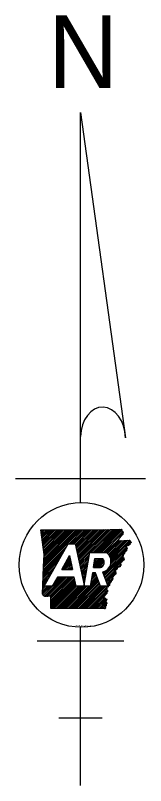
# Model space of a CAD drawing. Extents: x -17668 to 16999, y -17303 to 5867.
# Drawn here: x -11839 to -11576, y -15274 to -13718 of the extents above; entities that cross this region are included whole.
import ezdxf

# ---------------------------------------------------------------- set-up
doc = ezdxf.new("R2010")
doc.units = 0
doc.layers.add('48', color=7, linetype='Continuous')

msp = doc.modelspace()

# ---------------------------------------------------------------- linework, layer by layer
at = {"layer": '48'}
for p, q in [((-11707.1, -13913.8), (-11616.2, -14570.8)), ((-11707.1, -14701.7), (-11707.1, -13913.8)), ((-11838.7, -14653), (-11575.6, -14653)), ((-11786.9, -14758.1), (-11785.9, -14757.1)), ((-11786.6, -14761.2), (-11782.4, -14757.1)), ((-11786.2, -14764.3), (-11778.9, -14757.1)), ((-11785.8, -14767.4), (-11775.4, -14757.1)), ((-11785.4, -14770.5), (-11771.9, -14757.1)), ((-11785, -14773.6), (-11768.5, -14757.1)), ((-11784.6, -14776.7), (-11765, -14757.1)), ((-11784.2, -14779.8), (-11761.5, -14757.1)), ((-11783.9, -14782.9), (-11758, -14757.1)), ((-11783.5, -14786), (-11754.5, -14757.1)), ((-11783.1, -14789.1), (-11751, -14757.1)), ((-11782.7, -14792.2), (-11747.6, -14757.1)), ((-11782.3, -14795.3), (-11744.1, -14757.1)), ((-11781.9, -14798.4), (-11740.6, -14757.1)), ((-11781.8, -14833.1), (-11705.7, -14757)), ((-11781.7, -14829.5), (-11709.2, -14757)), ((-11781.6, -14825.9), (-11712.7, -14757)), ((-11781.5, -14822.3), (-11716.2, -14757)), ((-11781.5, -14801.5), (-11737.1, -14757.1)), ((-11781.3, -14818.7), (-11719.7, -14757)), ((-11781.2, -14815.1), (-11723.2, -14757)), ((-11781.2, -14804.6), (-11733.6, -14757.1)), ((-11781.1, -14811.5), (-11726.7, -14757.1)), ((-11781, -14807.9), (-11730.1, -14757.1)), ((-11730.1, -14784.9), (-11702.2, -14757)), ((-11726.6, -14784.9), (-11698.7, -14757)), ((-11723.1, -14784.9), (-11695.2, -14757)), ((-11719.6, -14784.9), (-11691.7, -14756.9)), ((-11717.5, -14786.2), (-11688.1, -14756.9)), ((-11716.9, -14789.1), (-11684.6, -14756.8)), ((-11716.2, -14791.9), (-11681.1, -14756.7)), ((-11715.6, -14794.8), (-11677.5, -14756.7)), ((-11715, -14797.7), (-11674, -14756.6)), ((-11714.4, -14800.5), (-11670.5, -14756.6)), ((-11713.8, -14803.4), (-11666.9, -14756.5)), ((-11713.2, -14806.3), (-11663.4, -14756.5)), ((-11712.6, -14809.1), (-11659.8, -14756.4)), ((-11711.9, -14812), (-11656.3, -14756.4)), ((-11711.3, -14814.9), (-11652.8, -14756.3)), ((-11710.7, -14817.7), (-11649.2, -14756.3)), ((-11710.1, -14820.6), (-11645.7, -14756.2)), ((-11709.5, -14823.5), (-11642.1, -14756.1)), ((-11685.3, -14802.8), (-11638.5, -14756)), ((-11681.8, -14802.8), (-11635, -14755.9)), ((-11678.3, -14802.8), (-11631.4, -14755.9)), ((-11674.8, -14802.8), (-11627.8, -14755.8)), ((-11671.4, -14802.8), (-11624.3, -14755.7)), ((-11667.9, -14802.8), (-11623.5, -14758.4)), ((-11664.4, -14802.8), (-11621.8, -14760.2)), ((-11660.9, -14802.8), (-11621.4, -14763.2)), ((-11657.4, -14802.8), (-11629.3, -14774.7)), ((-11654.3, -14803.1), (-11630, -14778.8)), ((-11652.4, -14804.7), (-11626.3, -14778.6)), ((-11650.7, -14806.5), (-11622.7, -14778.5)), ((-11649.2, -14808.4), (-11619, -14778.3)), ((-11647.9, -14810.6), (-11615.3, -14778.1)), ((-11646.8, -14813), (-11611.7, -14777.9)), ((-11646, -14815.7), (-11608.3, -14778.1)), ((-11645.5, -14818.7), (-11606.7, -14779.9)), ((-11608.3, -14784.9), (-11605.1, -14781.8)), ((-11781.9, -14836.7), (-11734.9, -14789.7)), ((-11780.8, -14870.7), (-11732.2, -14784.9)), ((-11732.2, -14784.9), (-11717.8, -14784.9)), ((-11646.2, -14826.4), (-11614.6, -14794.8)), ((-11645.5, -14822.2), (-11615, -14791.7)), ((-11782.2, -14843.9), (-11744, -14805.8)), ((-11782.1, -14840.3), (-11739.5, -14797.7)), ((-11745, -14837), (-11729.1, -14808.9)), ((-11731.6, -14813.3), (-11728.8, -14810.5)), ((-11708.9, -14826.4), (-11689.1, -14806.6)), ((-11708.3, -14829.2), (-11689.9, -14810.8)), ((-11688.4, -14802.8), (-11654.7, -14802.8)), ((-11660.6, -14847.8), (-11622, -14809.1)), ((-11659.7, -14850.3), (-11621.4, -14812)), ((-11649.3, -14832.9), (-11622.7, -14806.3)), ((-11618.5, -14802.2), (-11614.2, -14797.9)), ((-11782.4, -14851.1), (-11753.1, -14821.8)), ((-11782.3, -14847.5), (-11748.6, -14813.8)), ((-11744.9, -14837), (-11727, -14819.1)), ((-11741.4, -14837), (-11726.4, -14822)), ((-11740.7, -14829.4), (-11727.6, -14816.2)), ((-11737.9, -14837), (-11725.7, -14824.8)), ((-11736.2, -14821.3), (-11728.2, -14813.4)), ((-11734.4, -14837), (-11725.1, -14827.7)), ((-11707.7, -14832.1), (-11690.6, -14815)), ((-11707, -14835), (-11691.3, -14819.2)), ((-11706.4, -14837.8), (-11692.1, -14823.5)), ((-11705.8, -14840.7), (-11692.8, -14827.7)), ((-11681.1, -14833.2), (-11662.8, -14814.9)), ((-11680.4, -14829), (-11666.3, -14814.9)), ((-11679.7, -14824.8), (-11669.7, -14814.9)), ((-11678.9, -14820.6), (-11673.2, -14814.9)), ((-11678.2, -14816.4), (-11676.7, -14814.9)), ((-11677.9, -14814.9), (-11662.1, -14814.9)), ((-11677.6, -14833.2), (-11660.8, -14816.4)), ((-11674.1, -14833.2), (-11659.7, -14818.7)), ((-11670.7, -14833.2), (-11659, -14821.6)), ((-11667.2, -14833.2), (-11659.3, -14825.3)), ((-11658.7, -14852.8), (-11620.7, -14814.8)), ((-11657.8, -14855.4), (-11620.1, -14817.6)), ((-11632, -14833), (-11627.1, -14828.1)), ((-11782.6, -14858.3), (-11762.2, -14837.9)), ((-11782.5, -14854.7), (-11757.7, -14829.9)), ((-11745, -14837), (-11723.1, -14837)), ((-11730.9, -14837), (-11724.5, -14830.6)), ((-11727.5, -14837), (-11723.9, -14833.4)), ((-11724, -14837), (-11723.3, -14836.3)), ((-11705.2, -14843.6), (-11693.5, -14831.9)), ((-11704.6, -14846.4), (-11694.3, -14836.1)), ((-11704, -14849.3), (-11695, -14840.3)), ((-11684.1, -14850.3), (-11677.2, -14843.4)), ((-11683.4, -14846.1), (-11680.6, -14843.4)), ((-11677.1, -14843.4), (-11682.9, -14843.4)), ((-11681.1, -14833.2), (-11666.7, -14833.2)), ((-11667, -14870.7), (-11677.1, -14843.4)), ((-11662.8, -14841.9), (-11652.2, -14870.7)), ((-11662.5, -14842.7), (-11661.4, -14841.6)), ((-11661.6, -14845.2), (-11654.9, -14838.6)), ((-11656.9, -14857.9), (-11636, -14837)), ((-11655.9, -14860.5), (-11636.4, -14840.9)), ((-11782.9, -14865.5), (-11771.3, -14854)), ((-11782.8, -14861.9), (-11766.8, -14845.9)), ((-11782.3, -14889.3), (-11745.6, -14852.7)), ((-11780.2, -14890.7), (-11742.2, -14852.7)), ((-11777.7, -14891.7), (-11738.7, -14852.7)), ((-11773.5, -14891), (-11735.2, -14852.7)), ((-11770, -14891), (-11731.7, -14852.7)), ((-11767.3, -14891.7), (-11728.2, -14852.7)), ((-11767.2, -14898.6), (-11721.3, -14852.7)), ((-11767.2, -14895.1), (-11724.7, -14852.7)), ((-11767.1, -14902), (-11719.4, -14854.3)), ((-11767.1, -14905.5), (-11718.8, -14857.2)), ((-11753.9, -14852.7), (-11764.1, -14870.7)), ((-11760.2, -14863.7), (-11749.1, -14852.7)), ((-11755.6, -14855.7), (-11752.6, -14852.7)), ((-11719.8, -14852.7), (-11753.9, -14852.7)), ((-11732.3, -14915.9), (-11672.4, -14856)), ((-11728.8, -14915.9), (-11671.4, -14858.6)), ((-11703.4, -14852.2), (-11695.7, -14844.5)), ((-11702.7, -14855), (-11696.5, -14848.8)), ((-11702.1, -14857.9), (-11697.2, -14853)), ((-11701.5, -14860.8), (-11697.9, -14857.2)), ((-11687.1, -14867.2), (-11673.3, -14853.5)), ((-11686.3, -14863), (-11674.3, -14850.9)), ((-11685.6, -14858.8), (-11675.2, -14848.4)), ((-11684.8, -14854.6), (-11676.1, -14845.9)), ((-11655, -14863), (-11636.8, -14844.8)), ((-11654, -14865.6), (-11643.4, -14854.9)), ((-11653.1, -14868.1), (-11644.9, -14859.8)), ((-11783.6, -14887.1), (-11767.1, -14870.7)), ((-11783.5, -14883.5), (-11770.6, -14870.7)), ((-11783.4, -14879.9), (-11774.1, -14870.7)), ((-11783.2, -14876.3), (-11777.6, -14870.7)), ((-11783.1, -14872.7), (-11780.4, -14870)), ((-11783, -14869.1), (-11775.9, -14862)), ((-11764.1, -14870.7), (-11780.8, -14870.7)), ((-11767.1, -14909), (-11718.2, -14860.1)), ((-11767.1, -14912.5), (-11717.6, -14862.9)), ((-11767.1, -14915.9), (-11717, -14865.8)), ((-11763.6, -14915.9), (-11716.4, -14868.7)), ((-11760.1, -14915.9), (-11714.9, -14870.7)), ((-11756.6, -14915.9), (-11711.4, -14870.7)), ((-11753.2, -14915.9), (-11707.9, -14870.7)), ((-11749.7, -14915.9), (-11704.4, -14870.7)), ((-11746.2, -14915.9), (-11701, -14870.7)), ((-11742.7, -14915.9), (-11697.5, -14870.7)), ((-11739.2, -14915.9), (-11694, -14870.7)), ((-11735.8, -14915.9), (-11690.5, -14870.7)), ((-11725.3, -14915.9), (-11670.5, -14861.1)), ((-11721.9, -14916), (-11669.6, -14863.7)), ((-11718.4, -14916), (-11668.6, -14866.2)), ((-11687.7, -14870.7), (-11715.9, -14870.7)), ((-11714.9, -14916), (-11667.7, -14868.7)), ((-11711.4, -14916), (-11666.1, -14870.7)), ((-11707.9, -14916), (-11662.6, -14870.7)), ((-11704.5, -14916), (-11659.2, -14870.7)), ((-11701, -14916), (-11655.7, -14870.7)), ((-11700.9, -14863.6), (-11698.7, -14861.4)), ((-11700.3, -14866.5), (-11699.4, -14865.6)), ((-11697.5, -14916), (-11654.5, -14873)), ((-11652.2, -14870.7), (-11667, -14870.7)), ((-11694, -14916), (-11654.4, -14876.3)), ((-11690.6, -14916), (-11654.2, -14879.6)), ((-11687.1, -14916), (-11654, -14883)), ((-11683.6, -14916), (-11659.8, -14892.2)), ((-11680.1, -14916), (-11658.7, -14894.6)), ((-11676.7, -14916), (-11657.6, -14897)), ((-11673.2, -14916), (-11656.5, -14899.4)), ((-11669.7, -14916), (-11655.5, -14901.8)), ((-11666.2, -14916), (-11654.6, -14904.4)), ((-11662.7, -14916), (-11656.1, -14909.4)), ((-11659.3, -14916.1), (-11657.7, -14914.5)), ((-11707.1, -15273.5), (-11707.1, -14953.7)), ((-11794.8, -14980.9), (-11619.4, -14980.9)), ((-11751, -15136.7), (-11663.3, -15136.7))]:
    msp.add_line(p, q, dxfattribs=at)
for points in [[(-11787.1, -14757.1), (-11739, -14757.1), (-11696.8, -14757), (-11647.1, -14756.2), (-11624.1, -14755.7)], [(-11787.1, -14757.1), (-11739, -14757.1), (-11696.9, -14757), (-11647.1, -14756.2), (-11624.1, -14755.7)], [(-11781.8, -14831.7), (-11780.9, -14806.4), (-11787.1, -14757.1)], [(-11783.6, -14887.1), (-11780.9, -14806.4), (-11787.1, -14757.1)], [(-11609, -14777.8), (-11604.8, -14782.1), (-11615.2, -14790.6), (-11614.1, -14799.2), (-11622.9, -14805.1), (-11619.9, -14818.3), (-11626.8, -14824.6), (-11627.4, -14831.4), (-11635.7, -14834.4), (-11637, -14847.2), (-11643, -14853.6), (-11645.9, -14863.3), (-11654.6, -14871.2), (-11653.9, -14885.3), (-11659.9, -14892), (-11654.5, -14904.1), (-11658.2, -14916.1)], [(-11631.2, -14778.9), (-11608.6, -14777.7)], [(-11631.2, -14778.9), (-11608.6, -14777.7)], [(-11717.8, -14784.9), (-11699.9, -14868.4), (-11688.4, -14802.8)], [(-11729.1, -14808.9), (-11723.1, -14837)], [(-11681.1, -14833.2), (-11677.9, -14814.9)], [(-11783.6, -14887.1), (-11781.8, -14831.7)], [(-11682.9, -14843.4), (-11687.7, -14870.7)], [(-11715.9, -14870.7), (-11719.8, -14852.7)], [(-11658.2, -14916.1), (-11767.1, -14915.9), (-11767.2, -14891.8)], [(-11658.2, -14916.1), (-11767.1, -14915.9), (-11767.2, -14891.8)]]:
    msp.add_lwpolyline(points, dxfattribs=at)
for centre, major_axis, ratio, start_param, end_param in [((-11661.7, -14572.2), (-1.9, 63.2), 0.719778, 4.712385, 7.768526), ((-11667.3, -14820.6), (-21.8, 0), 0.999987, 1.777838, 4.099264), ((-11670.1, -14822.6), (-11.1, 0), 0.999987, 1.887169, 3.90762)]:
    msp.add_ellipse(centre, major_axis=major_axis, ratio=ratio, start_param=start_param, end_param=end_param, dxfattribs=at)
msp.add_ellipse((-11705.1, -14827.7), major_axis=(126, 0), ratio=0.999976, dxfattribs=at)
for points in [[(-11624.1, -14755.7), (-11623.9, -14757), (-11623.5, -14757.7), (-11623.5, -14758.9), (-11622.9, -14759.5), (-11622.1, -14760), (-11621.3, -14760.8), (-11621.1, -14761.8), (-11621.4, -14762.9), (-11621.4, -14764.1), (-11621.5, -14765.1), (-11621.7, -14766), (-11622.4, -14766.7), (-11623.1, -14767.3), (-11623.7, -14767.9), (-11624.2, -14768.6), (-11624.9, -14769.3), (-11625.7, -14770), (-11626.4, -14770.7), (-11627, -14771.5), (-11627.3, -14772.4), (-11627.9, -14773.1), (-11628.5, -14773.7), (-11629.2, -14774.5), (-11629.6, -14775.3), (-11630.2, -14776.2), (-11630.4, -14777.1), (-11630.8, -14777.8), (-11630.9, -14777.9)], [(-11624.1, -14755.7), (-11623.9, -14757), (-11623.5, -14757.7), (-11623.4, -14758.9), (-11622.9, -14759.5), (-11622.1, -14760), (-11621.3, -14760.9), (-11621.1, -14761.9), (-11621.4, -14762.9), (-11621.4, -14764.1), (-11621.5, -14765.1), (-11621.7, -14766), (-11622.4, -14766.7), (-11623.1, -14767.3), (-11623.7, -14767.9), (-11624.2, -14768.5), (-11625, -14769.3), (-11625.7, -14770), (-11626.3, -14770.7), (-11627, -14771.5), (-11627.3, -14772.4), (-11628, -14773.1), (-11628.5, -14773.7), (-11629.2, -14774.5), (-11629.6, -14775.3), (-11630.2, -14776.2), (-11630.4, -14777.1), (-11630.8, -14777.8), (-11630.9, -14777.9)], [(-11609, -14777.8), (-11608.6, -14777.7), (-11607.6, -14778.8), (-11607.2, -14779.7), (-11606.5, -14780.2), (-11605.8, -14780.5), (-11605.2, -14781.1), (-11604.8, -14781.9), (-11605, -14782.6), (-11605.9, -14782.6), (-11606.8, -14782.8), (-11607.7, -14782.7), (-11608.4, -14783.3), (-11607.7, -14784.1), (-11606.9, -14784.9), (-11606.6, -14785.7), (-11607.1, -14786.4), (-11608.1, -14786.9), (-11609, -14787.2), (-11609.8, -14787.9), (-11610.2, -14788.6), (-11611.1, -14788.9), (-11612.1, -14789.2), (-11612.9, -14789.3), (-11613.9, -14789.5), (-11614.8, -14789.9), (-11615.2, -14790.7), (-11615.1, -14791.7), (-11615.1, -14792.9), (-11614.1, -14793.3), (-11613.3, -14793.3), (-11612.4, -14793.8), (-11612.5, -14794.4), (-11613.1, -14795.3), (-11613.9, -14795.9), (-11614.6, -14796.2), (-11615.3, -14796.9), (-11615.1, -14797.5), (-11614.4, -14797.9), (-11614, -14798.6), (-11614.1, -14799.2), (-11614.8, -14799.7), (-11615.5, -14799.5), (-11616.1, -14798.7), (-11616.7, -14798.5), (-11617.3, -14798.2), (-11618, -14798.6), (-11618, -14799.5), (-11618.2, -14800.4), (-11618, -14801.1), (-11617.8, -14802), (-11617.8, -14802.7), (-11618, -14803.8), (-11618.5, -14804.8), (-11619.1, -14805.1), (-11619.4, -14804), (-11619.5, -14803.1), (-11619.8, -14802.5), (-11620.3, -14802.5), (-11620.9, -14803), (-11621.6, -14803.6), (-11622.4, -14804.4), (-11623, -14805.1), (-11622.7, -14806), (-11622, -14806.3), (-11621.5, -14806.1), (-11621.3, -14805.5), (-11620.8, -14805.4), (-11620.3, -14806.4)], [(-11620.3, -14806.4), (-11620.2, -14807.2), (-11620.7, -14808.1), (-11620.9, -14809), (-11620.8, -14810), (-11621.7, -14810.5), (-11622.5, -14811.1), (-11622.1, -14811.8), (-11621.2, -14812.4), (-11620.3, -14812.9), (-11619.7, -14813.5), (-11619.6, -14814.7), (-11619.4, -14815.4), (-11619.1, -14816.5), (-11619, -14817.3), (-11619.5, -14818.1), (-11620.2, -14818.3), (-11620.8, -14818.1), (-11621.6, -14818.1), (-11622.2, -14818.6), (-11622.7, -14819.5), (-11623.1, -14820.3), (-11623.5, -14821), (-11623.8, -14821.8), (-11624.4, -14822.7), (-11625.2, -14822.8), (-11626.2, -14823.1), (-11626.7, -14823.7), (-11626.6, -14824.8), (-11626.1, -14825.6), (-11625.7, -14826.5), (-11625.4, -14827.3), (-11625.5, -14828.3), (-11626, -14829.1), (-11626.5, -14829.5), (-11626.7, -14830.4), (-11627.1, -14831.2), (-11627.5, -14831.4), (-11628.2, -14831.3), (-11629, -14831.2), (-11629.6, -14831.3), (-11630.2, -14831.6), (-11630.9, -14831.4), (-11631.5, -14830.6), (-11632.1, -14830.1), (-11632.7, -14829.9), (-11633.3, -14830.2), (-11633.4, -14831.2), (-11633.1, -14832.2), (-11632.8, -14833.6), (-11633.1, -14834.4), (-11633.2, -14835.8)], [(-11633.2, -14835.8), (-11634.2, -14836.6), (-11634.7, -14837.4), (-11637.3, -14837.2), (-11637.3, -14838.1), (-11638.2, -14838.6), (-11639, -14839.2), (-11638.6, -14839.9), (-11637.7, -14840.6), (-11636.8, -14841.1), (-11636.2, -14841.6), (-11636.1, -14842.8), (-11635.9, -14843.6), (-11635.6, -14844.6), (-11635.5, -14845.4), (-11636, -14846.3), (-11636.7, -14846.4), (-11637.3, -14846.2), (-11638.1, -14846.2), (-11638.7, -14846.8), (-11639.1, -14847.6), (-11639.6, -14848.4), (-11639.9, -14849.1), (-11640.3, -14849.9), (-11640.9, -14850.8), (-11641.7, -14851), (-11642.7, -14851.2), (-11643.2, -14851.8), (-11643.1, -14853), (-11642.6, -14853.7), (-11642.2, -14854.6), (-11641.9, -14855.4), (-11642, -14856.4), (-11642.4, -14857.2), (-11643, -14857.6), (-11643.2, -14858.6), (-11643.6, -14859.3), (-11644, -14859.5), (-11644.7, -14859.4), (-11645.4, -14859.3), (-11646.1, -14859.4), (-11646.7, -14859.7), (-11647.4, -14859.5), (-11648, -14858.8), (-11648.5, -14858.2), (-11649.1, -14858), (-11649.8, -14858.3), (-11649.9, -14859.3), (-11649.6, -14860.3), (-11649.3, -14861.7), (-11649.6, -14862.5), (-11649.7, -14863.9)], [(-11653.7, -14875.1), (-11653.9, -14875.8), (-11654.3, -14877), (-11654.2, -14878), (-11653.7, -14878.8), (-11653, -14879.3), (-11652.2, -14880), (-11652.3, -14881.1), (-11652.8, -14881.4), (-11653.8, -14881.2), (-11654.6, -14880.8), (-11655.3, -14881), (-11656.2, -14881.5), (-11656.9, -14881.6), (-11656.9, -14883), (-11656, -14884), (-11655.2, -14884), (-11654.2, -14884.1), (-11653.9, -14885.2), (-11654.4, -14886.1), (-11655.3, -14886.5), (-11656.4, -14886), (-11657.2, -14885.4), (-11658.1, -14884.9), (-11659.1, -14884.6), (-11659.6, -14884.7), (-11659.9, -14886), (-11659.4, -14887.1), (-11658.7, -14887.9), (-11657.9, -14888.9), (-11658.1, -14889.7), (-11658.6, -14889.8), (-11659.5, -14890.1), (-11660.1, -14890.3), (-11660.2, -14890.6), (-11660, -14891.6), (-11659.7, -14892.7), (-11659.7, -14893.5), (-11660, -14894.3), (-11660.5, -14895.5), (-11660.5, -14896.2), (-11660.1, -14896.6), (-11659.7, -14896.5), (-11659.1, -14896.1), (-11658.7, -14895.6), (-11658.3, -14895), (-11657.7, -14894.5), (-11657, -14895), (-11656.8, -14895.9), (-11657.2, -14896.7), (-11657.9, -14897), (-11658.6, -14897.3), (-11659.2, -14898), (-11659, -14898.8), (-11658.6, -14899.2), (-11657.5, -14899), (-11656.8, -14898.6), (-11656.3, -14898.2), (-11655.8, -14897.7), (-11655.6, -14897.2), (-11655.2, -14896.7), (-11654.5, -14896.5), (-11654.2, -14897), (-11654.3, -14898), (-11654.7, -14898.9), (-11655.3, -14899.7), (-11655.9, -14900.3), (-11656.7, -14901.5), (-11656.5, -14902.6), (-11656.2, -14903.6), (-11655.8, -14904.3), (-11655.1, -14904.1), (-11654.3, -14904), (-11653.8, -14904.4), (-11653.9, -14905.3), (-11654.5, -14906.1), (-11655, -14906.8), (-11655.3, -14907.9), (-11655.2, -14908.7), (-11655.2, -14909.3), (-11655.4, -14910.1), (-11655.8, -14910.5), (-11657, -14910.5), (-11658.1, -14910.4), (-11658.7, -14910.7), (-11658.6, -14911.7), (-11657.9, -14912.5), (-11657.5, -14912.8), (-11656.8, -14913.7), (-11656.5, -14914.4), (-11656.6, -14915), (-11657, -14915.5), (-11658.2, -14916.1)], [(-11653.7, -14875.1), (-11653.9, -14875.8), (-11654.3, -14877), (-11654.2, -14878), (-11653.7, -14878.8), (-11653, -14879.3), (-11652.2, -14880), (-11652.3, -14881.1), (-11652.8, -14881.4), (-11653.8, -14881.2), (-11654.6, -14880.8), (-11655.3, -14881), (-11656.2, -14881.5), (-11656.9, -14881.6), (-11656.9, -14883), (-11656, -14884), (-11655.2, -14884), (-11654.2, -14884.1), (-11653.9, -14885.2), (-11654.4, -14886.1), (-11655.3, -14886.5), (-11656.4, -14886), (-11657.2, -14885.4), (-11658.1, -14884.9), (-11659.1, -14884.6), (-11659.6, -14884.7), (-11659.9, -14886), (-11659.4, -14887.1), (-11658.7, -14887.9), (-11657.9, -14888.9), (-11658.1, -14889.7), (-11658.6, -14889.8), (-11659.5, -14890.1), (-11660.1, -14890.3), (-11660.2, -14890.6), (-11660, -14891.6), (-11659.7, -14892.7), (-11659.7, -14893.5), (-11660, -14894.3), (-11660.5, -14895.5), (-11660.5, -14896.2), (-11660.1, -14896.6), (-11659.7, -14896.5), (-11659.1, -14896.1), (-11658.7, -14895.6), (-11658.3, -14895), (-11657.7, -14894.5), (-11657, -14895), (-11656.8, -14895.9), (-11657.2, -14896.7), (-11657.9, -14897), (-11658.6, -14897.3), (-11659.2, -14898), (-11659, -14898.8), (-11658.6, -14899.2), (-11657.5, -14899), (-11656.8, -14898.6), (-11656.3, -14898.2), (-11655.8, -14897.7), (-11655.6, -14897.2), (-11655.2, -14896.7), (-11654.5, -14896.5), (-11654.2, -14897), (-11654.3, -14898), (-11654.7, -14898.9), (-11655.3, -14899.7), (-11655.9, -14900.3), (-11656.7, -14901.5), (-11656.5, -14902.6), (-11656.2, -14903.6), (-11655.8, -14904.3), (-11655.1, -14904.1), (-11654.3, -14904), (-11653.8, -14904.4), (-11653.9, -14905.3), (-11654.5, -14906.1), (-11655, -14906.8), (-11655.3, -14907.9), (-11655.2, -14908.7), (-11655.2, -14909.3), (-11655.4, -14910.1), (-11655.8, -14910.5), (-11657, -14910.5), (-11658.1, -14910.4), (-11658.7, -14910.7), (-11658.6, -14911.7), (-11657.9, -14912.5), (-11657.5, -14912.8), (-11656.8, -14913.7), (-11656.5, -14914.4), (-11656.6, -14915), (-11657, -14915.5), (-11658.2, -14916.1)], [(-11649.7, -14863.9), (-11649.7, -14864), (-11650.3, -14864.6), (-11650, -14865.7), (-11648.8, -14866.1), (-11648.3, -14867.1), (-11648.3, -14868), (-11648.6, -14869.2), (-11649.2, -14869.8), (-11650.2, -14870), (-11651, -14870.2), (-11651.1, -14871.5), (-11651.5, -14872.2), (-11652.1, -14872.4), (-11653, -14872), (-11653.5, -14871.8), (-11654.2, -14871.5), (-11655, -14871), (-11655.7, -14871.1), (-11655.5, -14872.4), (-11655.4, -14872.4), (-11654.7, -14873.4), (-11654, -14874.2), (-11653.7, -14875.1)], [(-11649.7, -14863.9), (-11649.7, -14864), (-11650.3, -14864.6), (-11650, -14865.7), (-11648.8, -14866.1), (-11648.3, -14867.1), (-11648.3, -14868), (-11648.6, -14869.2), (-11649.2, -14869.8), (-11650.2, -14870), (-11651, -14870.2), (-11651.1, -14871.5), (-11651.5, -14872.2), (-11652.1, -14872.4), (-11653, -14872), (-11653.5, -14871.8), (-11654.2, -14871.5), (-11655, -14871), (-11655.7, -14871.1), (-11655.5, -14872.4), (-11655.4, -14872.4), (-11654.7, -14873.4), (-11654, -14874.2), (-11653.7, -14875.1)], [(-11767.2, -14891.8), (-11767, -14891.9), (-11767.6, -14891.5), (-11768.4, -14891.1), (-11769.3, -14891.1), (-11770.4, -14890.9), (-11771.3, -14890.8), (-11772.2, -14890.2), (-11773.2, -14890.8), (-11774.4, -14891.3), (-11775, -14890.8), (-11775.9, -14891.2), (-11776.5, -14891), (-11777.5, -14891.7), (-11778.5, -14891.4), (-11779.2, -14891.6), (-11780.1, -14891.6), (-11780.3, -14890.6), (-11781.1, -14890.4), (-11781.9, -14890), (-11782.4, -14889), (-11782.7, -14888.2), (-11783.6, -14887.1)], [(-11767.2, -14891.8), (-11767.1, -14891.9), (-11767.6, -14891.5), (-11768.4, -14891.1), (-11769.2, -14891.1), (-11770.3, -14890.9), (-11771.3, -14890.8), (-11772.2, -14890.2), (-11773.2, -14890.9), (-11774.4, -14891.3), (-11775, -14890.8), (-11775.9, -14891.2), (-11776.5, -14891), (-11777.5, -14891.7), (-11778.5, -14891.4), (-11779.2, -14891.6), (-11780.1, -14891.6), (-11780.3, -14890.6), (-11781.1, -14890.4), (-11781.9, -14890), (-11782.4, -14889), (-11782.7, -14888.2), (-11783.6, -14887.1)]]:
    msp.add_spline(points, degree=3, dxfattribs=at)

# ---------------------------------------------------------------- texts
for s, height, p in [('N', 146.7, (-11772.5, -13864.2)), ('STS 10-03-17', 3.644, (-11717.1, -14952.7))]:
    msp.add_text(s, height=height, dxfattribs=at).set_placement(p)

doc.saveas('drawing.dxf')
